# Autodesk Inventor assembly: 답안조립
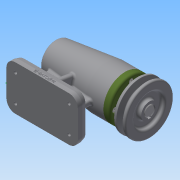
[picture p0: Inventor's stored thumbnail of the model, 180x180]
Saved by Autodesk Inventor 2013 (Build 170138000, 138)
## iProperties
Created: 2017-01
Part Number: 답안조립
Document SubType Name: Assembly
Designer: Administrator
Author: Administrator
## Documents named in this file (12)
- C:\Users\Administrator\Desktop\470108V1006\답안조립.iam
- C:\Users\Administrator\Desktop\470108V1006\본체.ipt
- C:\Users\Administrator\Desktop\470108V1006\축.ipt
- C:\Users\Administrator\Desktop\470108V1006\베어링 51202.ipt
- C:\Users\Administrator\Desktop\470108V1006\어댑터슬리브.ipt
- C:\Users\Administrator\Desktop\470108V1006\베어링 6004.ipt
- C:\Users\Administrator\Desktop\470108V1006\볼트 M4 x 12.ipt
- C:\Users\Administrator\Desktop\470108V1006\커버.ipt
- C:\Users\Administrator\Desktop\470108V1006\오일 실.ipt
- C:\Users\Administrator\Desktop\470108V1006\키 5 x 5 x 16.ipt
- C:\Users\Administrator\Desktop\470108V1006\멈춤나사 M3x8.ipt
- C:\Users\Administrator\Desktop\470108V1006\V벨트풀리.ipt
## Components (6 placed, 2 different names)
1. ISO 4762 M4 x 12:1
2. V벨트풀리:1
3. ISO 4762 M4 x 12:2
4. ISO 4762 M4 x 12:3
5. ISO 4762 M4 x 12:4
6. ISO 4762 M4 x 12:5
